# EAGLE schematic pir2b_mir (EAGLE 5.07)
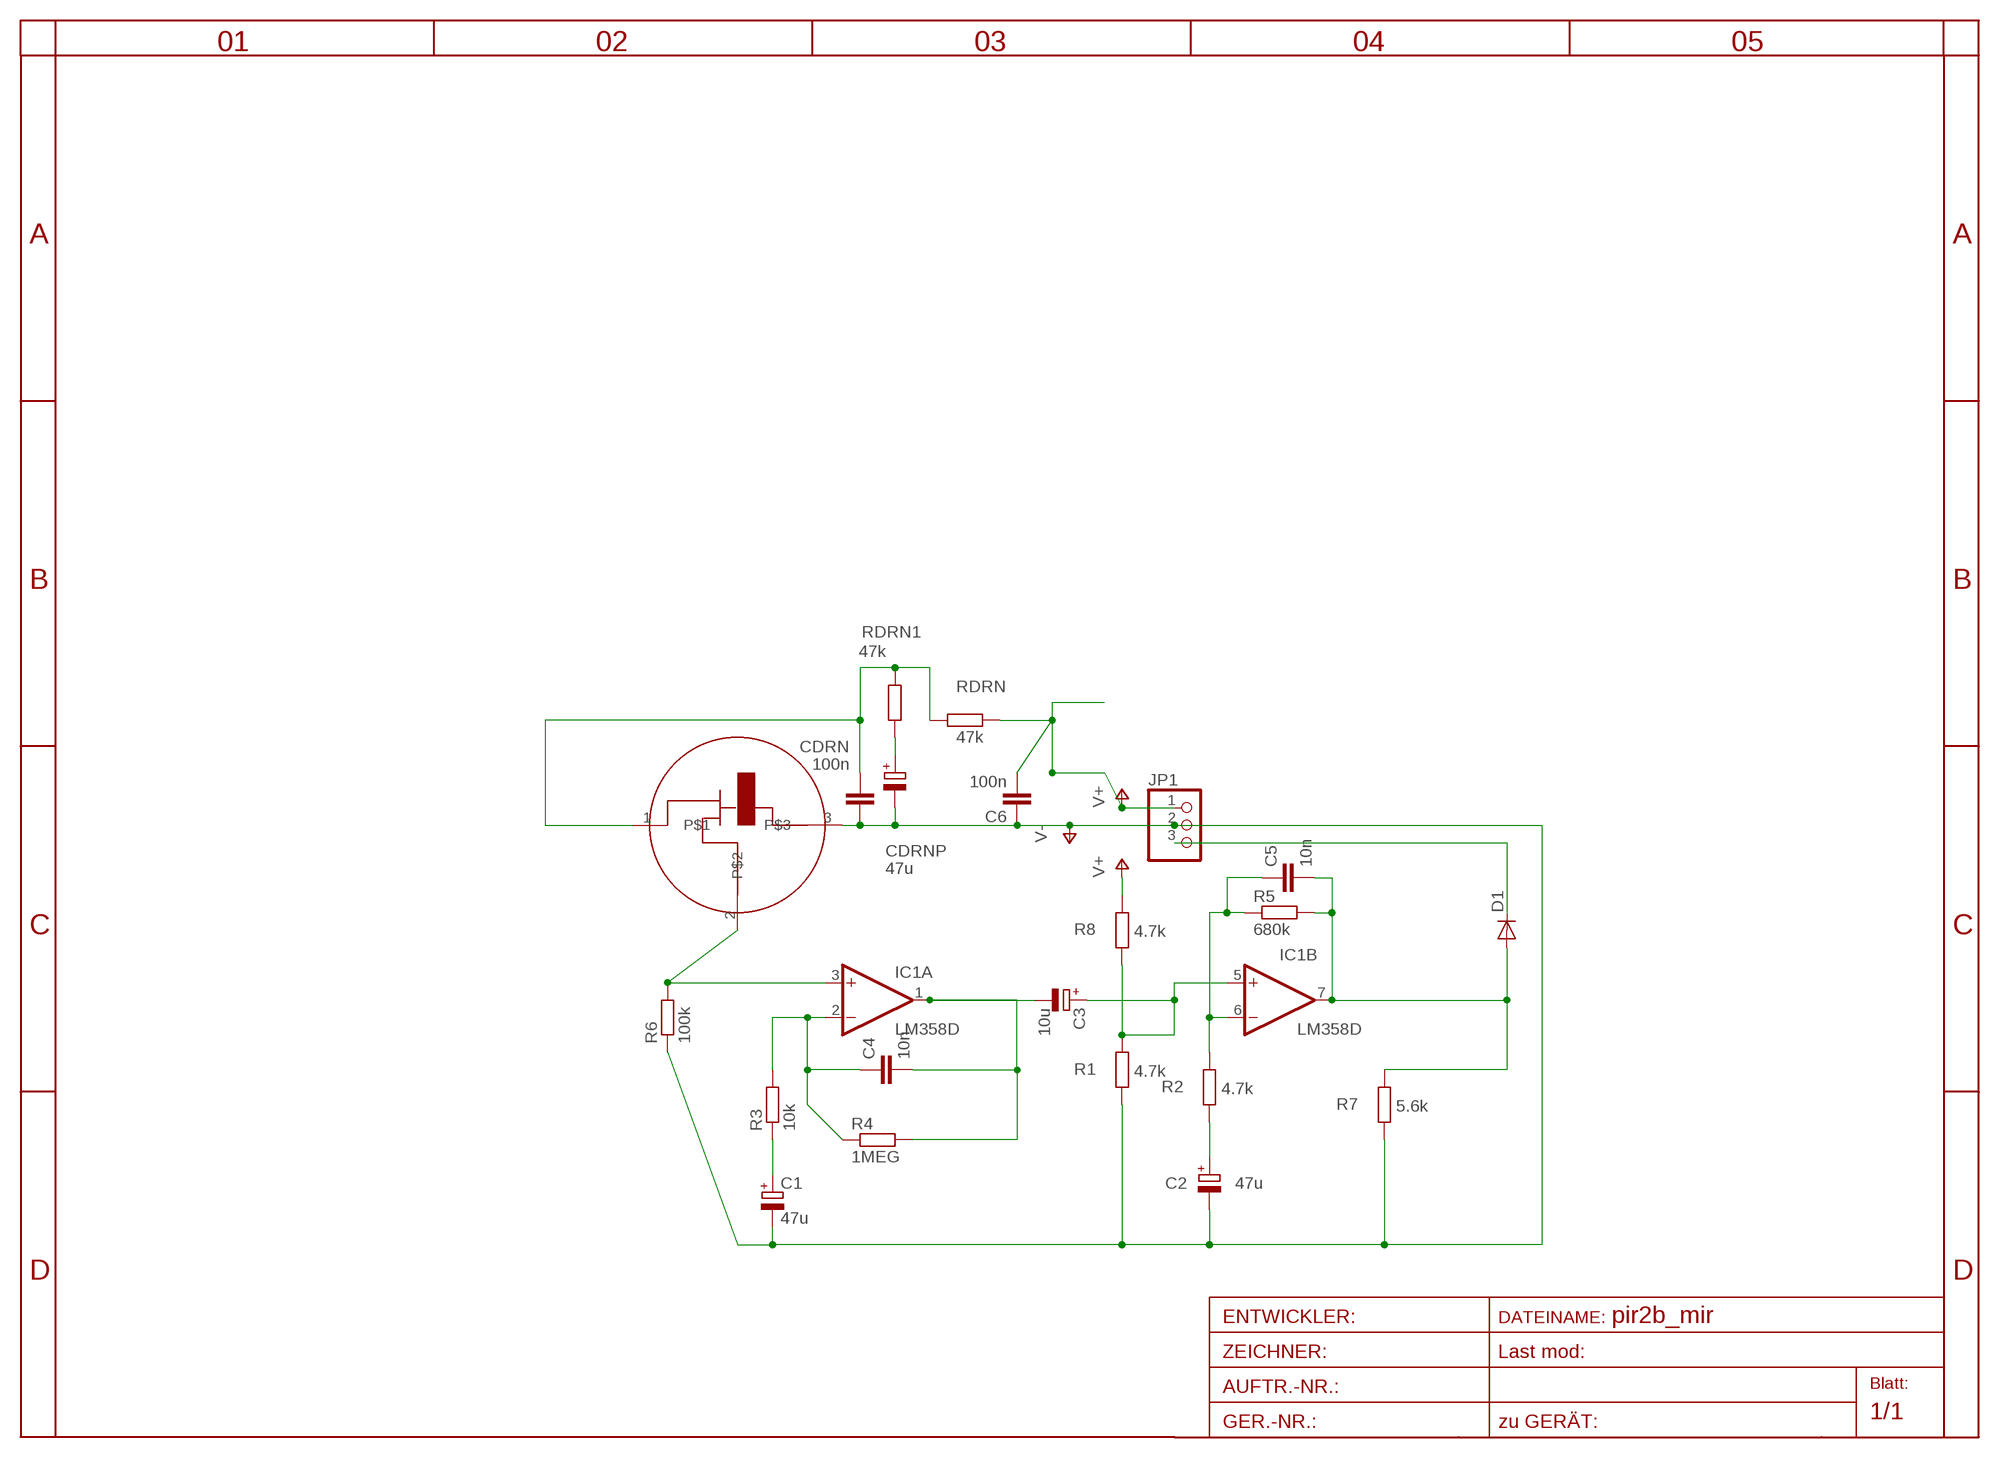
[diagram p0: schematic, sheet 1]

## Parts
C1  47u  CPOL-EUTT2D4L  [TT2D4L]
C2  47u  CPOL-EUTT24LR  [TT24LR]
C3  10u  CPOL-EUTT24LR  [TT24LR]
C4  10n  C-EUC0805  [C0805]
C5  10n  C-EUC0805  [C0805]
C6  100n  C-EUC0805  [C0805]
CDRN  100n  C-EUC1206  [C1206]
CDRNP  47u  CPOL-EUTT2D4L  [TT2D4L]
D1  DIODE-MINIMELF  [MINIMELF]
IC1  LM358D  [SO08]
JP1  PINHD-1X3  [1X03]
PIR  RE200B  [R200B]
R1  4.7k  R-EU_R0805  [R0805]
R2  4.7k  R-EU_R0805  [R0805]
R3  10k  R-EU_R1206  [R1206]
R4  1MEG  R-EU_R0805  [R0805]
R5  680k  R-EU_R0805  [R0805]
R6  100k  R-EU_R0805  [R0805]
R7  5.6k  R-EU_R0805  [R0805]
R8  4.7k  R-EU_R0805  [R0805]
RDRN  47k  R-EU_R0805  [R0805]
RDRN1  47k  R-EU_R0805  [R0805]

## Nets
DRN: CDRN.2 PIR.1 RDRN1.2 RDRN.1
N$1: C5.2 D1.A IC1.7(B:OUT) R5.2 R7.2
N$2: C3.+ IC1.5(B:+IN) R1.2 R8.1
N$3: D1.C JP1.3
N$4: IC1.3(A:+IN) PIR.2 R6.2
N$5: C4.1 IC1.2(A:-IN) R3.2 R4.1
N$6: C1.+ R3.1
N$7: C3.- C4.2 IC1.1(A:OUT) R4.2
N$9: C5.1 IC1.6(B:-IN) R2.2 R5.1
N$10: C2.+ R2.1
N$11: CDRNP.+ RDRN1.1
V+: C6.2 JP1.1 R8.2 RDRN.2
V-: C1.- C2.- C6.1 CDRN.1 CDRNP.- JP1.2 PIR.3 R1.1 R6.1 R7.1

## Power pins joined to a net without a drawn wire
V+: IC1.8(P:V+)
V-: IC1.4(P:V-)

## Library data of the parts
C1-C3 CDRNP = rcl:CPOL-EU: POLARIZED CAPACITOR, European symbol
C4-C6 CDRN = rcl:C-EU: CAPACITOR, European symbol
D1 = diode-1:DIODE-: DIODE
IC1 = linear:LM358: OP AMP also LM158; LM258; LM2904 Source: http://cache.national.com/ds/LM/LM158.pdf
JP1 = pinhead:PINHD-1X3: PIN HEADER
PIR = photo-elements:RE200B
R1-R8 RDRN RDRN1 = rcl:R-EU_: RESISTOR, European symbol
